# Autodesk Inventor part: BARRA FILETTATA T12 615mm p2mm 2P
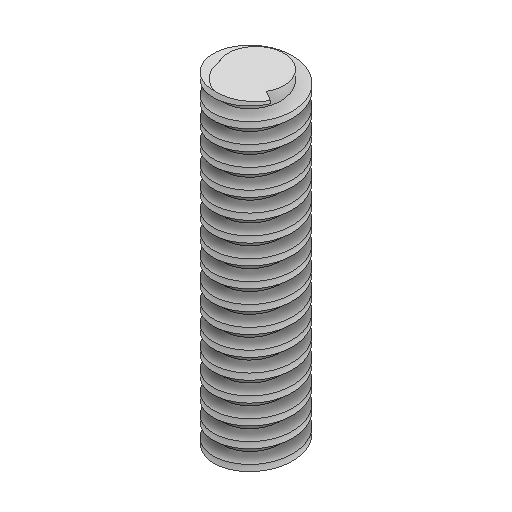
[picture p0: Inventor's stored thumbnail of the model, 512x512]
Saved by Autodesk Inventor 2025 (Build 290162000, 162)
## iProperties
Created: 2024-09
Part Number: BARRA FILETTATA T12 615mm p2mm 2P
Material: Generico
Document SubType Name: Modeling
Designer: R5800u
Density: 1 g/cm^3
Appearance: Default
Author: R5800u
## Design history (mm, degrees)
sketch "Schizzo1"
  geometry: C1 r 4.25 at (0, 0); 1 further point
  constraints: 1 centre point, 1 coincident
  dimensions: "d0" = 8.5 diameter of C1 (= Dn - Passo - 2 x Gioco)
extrude "Estrusione1" new body sketch "Schizzo1" distance "d1" = 50 (= Lunghezza); taper "d2" = 0 deg
sketch "Schizzo2"
  geometry: L1 (0, -4.25)-(0, 4.25) reference; L2 (0, -4.25)-(-0.469, -6); L3 (-0.469, -6)-(-1.41, -6); L4 (-1.41, -6)-(-1.879, -4.25); L5 (-1.879, -4.25)-(0, -4.25); L6 (-0.94, -6)-(-0.94, -4.25); L7 (-2.44, -5.479)-(-2.44, -3.693); L8 (-4.879, -4.25)-(-4.41, -6); L9 (-4.41, -6)-(-3.469, -6); L10 (-3.469, -6)-(-3, -4.25); L11 (-3, -4.25)-(-4.879, -4.25); L12 (-3.94, -6)-(-3.94, -4.25); L13 (0, 0)-(-5.844, 0); L14 (-1.879, 4.25)-(0, 4.25); L15 (-4.879, 4.25)-(-4.41, 6); L16 (-4.41, 6)-(-3.469, 6); L17 (-3.94, 6)-(-3.94, 4.25); L18 (-3.469, 6)-(-3, 4.25); L19 (0, 4.25)-(-0.469, 6); L20 (-0.469, 6)-(-1.41, 6); L21 (-0.94, 6)-(-0.94, 4.25); L22 (-1.41, 6)-(-1.879, 4.25); L23 (-2.44, 5.479)-(-2.44, 3.693); L24 (-3, 4.25)-(-4.879, 4.25); 4 further points
  constraints: 46 end point, 22 symmetric about line, 4 midpoint, 3 horizontal, 1 point on line, 1 vertical
  dimensions: "d28" = 75 deg angle of L5 L2; "d29" = 75 deg angle of L5 L4; "d30" = 1.75 distance of L6.start L6.end (= Gioco + 0.5 x Passo); "d31" = 3 distance of point (-3.94, -6) L6.start (= Passo); "d32" = 30 deg angle of L10 L4 (derived); "d47" = 4.25 distance from line of L13.start L5 (= -Gioco - 0.5 x Passo + 0.5 x Dn); "d49" = 1.87933 distance of L4.end L2.start (derived)
feature "Elicoide1" sketch "Schizzo2" pitch "d17" = 3 (= Passo); turns "d19" = 1; dims "d18" = 50 (= Lunghezza), "d20" = 0, angle "d21" = 90 deg, angle "d22" = 90 deg, "d23" = 0, "d24" = 0
sketch "Schizzo3"
  geometry: C1 r 7.186 at (0, 0); 1 further point
  constraints: 1 centre point, 1 coincident
extrude "Estrusione2" cut sketch "Schizzo3" distance "d33" = 25.725; taper "d34" = 0 deg
sketch "Schizzo4"
  geometry: C1 r 10.213 at (0, 0); 1 further point
  constraints: 1 centre point, 1 coincident
extrude "Estrusione3" cut sketch "Schizzo4" distance "d35" = 1; taper "d36" = 0 deg
fillet "Raccordo1" dims "d37" = 0.25
fillet "Raccordo2" dims "d38" = 0.13
node "Solido1"
other parameters: "Dn" = 12 [user parameter; used in 2 equation terms], "Passo" = 3 [user parameter; used in 5 equation terms], "Gioco" = 0.25 [user parameter; used in 3 equation terms], "Lunghezza" = 50 [user parameter; used in 2 equation terms]
